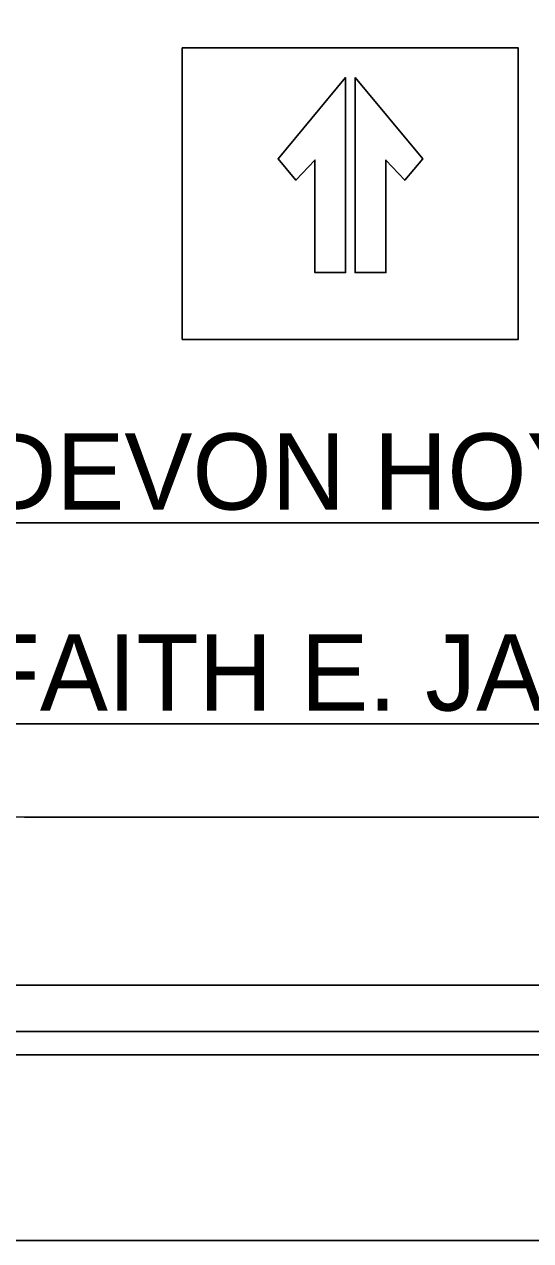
# Model space of a CAD drawing. Extents: x 2046816 to 2049224, y 578750 to 586986.
# Drawn here: x 2047791.4 to 2047845.8, y 585890.8 to 586021.7 of the extents above; entities that cross this region are included whole.
import ezdxf

# ---------------------------------------------------------------- set-up
doc = ezdxf.new("R2010")
doc.units = 0
for name, color, linetype in [('Default', 7, 'Continuous'), ('Sheet Data Field CELL', 7, 'Continuous'), ('Sheet Plot Border Inside CELL', 7, 'Continuous'), ('Sheet Plot Border Outside CELL', 7, 'Continuous'), ('Sheet Title CELL', 7, 'Continuous')]:
    doc.layers.add(name, color=color, linetype=linetype)

msp = doc.modelspace()

# ---------------------------------------------------------------- linework, layer by layer
at = {"layer": 'Default'}
for points in [[(2047844.5, 586019.2), (2047808.35, 586019.2), (2047808.35, 585987.82), (2047844.5, 585987.82), (2047844.5, 586019.2)], [(2047825.93, 586015.99), (2047825.93, 585995.01), (2047822.63, 585995.01), (2047822.63, 586007.11), (2047820.58, 586004.95), (2047818.66, 586007.24), (2047825.93, 586015.99)], [(2047818.66, 586007.24), (2047820.58, 586004.95), (2047822.63, 586007.11), (2047822.63, 585995.01), (2047825.93, 585995.01), (2047825.93, 586015.99), (2047818.66, 586007.24)], [(2047826.95, 586015.99), (2047826.95, 585995.01), (2047830.26, 585995.01), (2047830.26, 586007.11), (2047832.3, 586004.95), (2047834.23, 586007.24), (2047826.95, 586015.99)]]:
    msp.add_lwpolyline(points, dxfattribs=at)
for points in [[(2047808.35, 586019.2), (2047844.5, 586019.2), (2047844.5, 585987.82), (2047808.35, 585987.82)], [(2047826.95, 586015.99), (2047826.95, 585995.01), (2047830.26, 585995.01), (2047830.26, 586007.11), (2047832.3, 586004.95), (2047834.23, 586007.24)]]:
    msp.add_lwpolyline(points, close=True, dxfattribs=at)
at = {"layer": 'Sheet Plot Border Inside CELL'}
msp.add_lwpolyline([(2047553.67, 585910.81), (2049219.66, 585910.81), (2049219.66, 586965.81), (2047553.67, 586965.81)], close=True, dxfattribs=at)
at = {"layer": 'Sheet Plot Border Outside CELL'}
msp.add_lwpolyline([(2049224.17, 586985.81), (2047540.67, 586985.81), (2047540.67, 585890.81), (2049224.17, 585890.81)], close=True, dxfattribs=at)
at = {"layer": 'Sheet Title CELL'}
for p, q in [((2047786.89, 585968.08), (2047942.04, 585968.07)), ((2047786.34, 585946.44), (2047942.59, 585946.44)), ((2047791.37, 585936.39), (2048182.04, 585936.39)), ((2047772.18, 585918.31), (2049192.16, 585918.31))]:
    msp.add_line(p, q, dxfattribs=at)
msp.add_lwpolyline([(2047722.16, 585913.31), (2049192.16, 585913.31)], dxfattribs=at)
msp.add_arc((2047791.37, 585946.39), 10, 180, 270, dxfattribs=at)

# ---------------------------------------------------------------- texts
at = {"layer": 'Sheet Data Field CELL'}
for s, p in [('DEVON HOYLE, EI', (2047786.89, 585969.5)), ('FAITH E. JAHNKE, PE', (2047786.34, 585947.86))]:
    msp.add_text(s, height=8.2032, dxfattribs=at).set_placement(p)

doc.saveas('drawing.dxf')
